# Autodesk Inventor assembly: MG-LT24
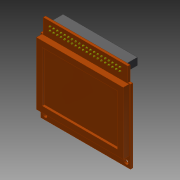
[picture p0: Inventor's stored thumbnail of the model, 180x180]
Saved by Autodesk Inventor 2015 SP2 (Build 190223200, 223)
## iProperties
Created: 2015-08
Part Number: MG-LT24
Document SubType Name: Assembly
Designer: rYan
Mass: 20.3599 g
Surface Area: 121.524 cm^2
Volume: 15.2846 cm^3
Density: 1.33205 g/cm^3
Author: rYan
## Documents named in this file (3)
- D:\Tigers SVN\mechanik\2016\Inventor\Kaufteile\MG-LT24.iam
- D:\Tigers SVN\mechanik\2016\Inventor\Kaufteile\LT24.ipt
- D:\Tigers SVN\mechanik\2016\Inventor\Kaufteile\SSW-120-01-F-D\SSW-120-01-F-D.iam
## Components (2 placed, 2 different names)
1. LT24:1 — Passend:1, Fluchtend:1, Fluchtend:2
2. SSW-120-01-F-D:1 [sub-assembly] — Passend:1, Fluchtend:1, Fluchtend:2
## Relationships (3: Flush 2, Mate 1)
- Passend:1 [Mate]: LT24:1 ↔ SSW-120-01-F-D:1
- Fluchtend:1 [Flush]: LT24:1 ↔ SSW-120-01-F-D:1
- Fluchtend:2 [Flush]: LT24:1 ↔ SSW-120-01-F-D:1
